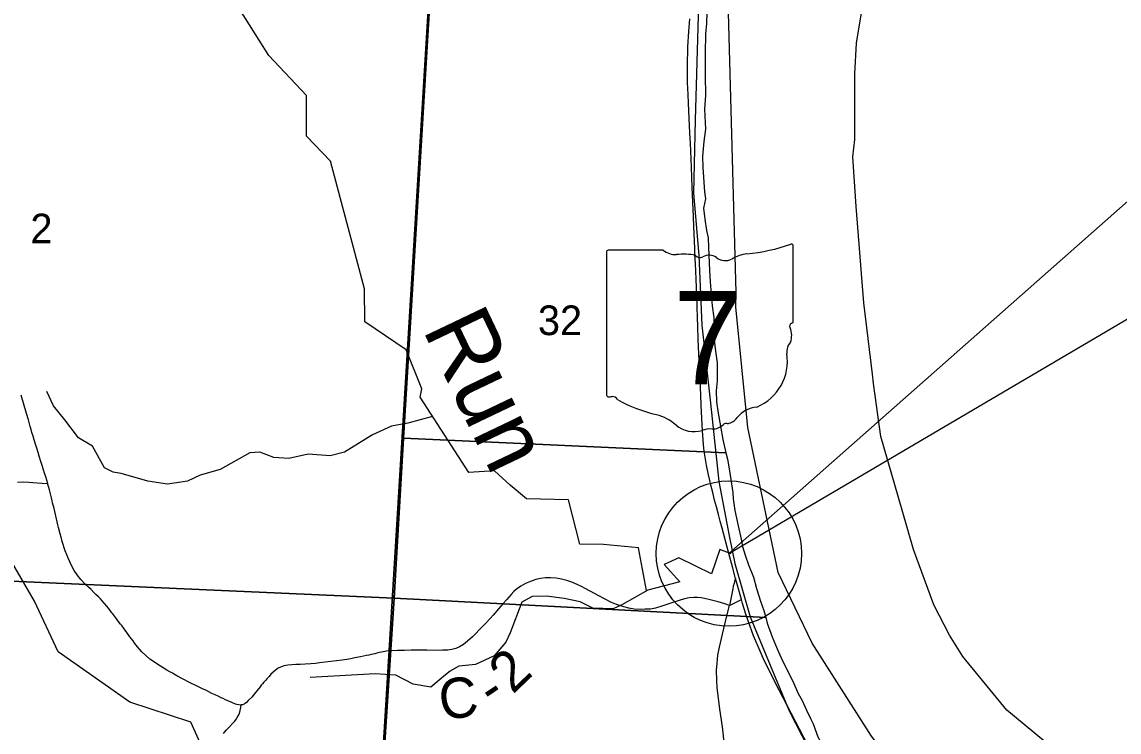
# Model space of a CAD drawing. Extents: x 21.4 to 65.3, y 4 to 26.
# Drawn here: x 25.873 to 27.421, y 21.246 to 22.248 of the extents above; entities that cross this region are included whole.
import ezdxf

# ---------------------------------------------------------------- set-up
doc = ezdxf.new("R2010")
doc.units = 0
for name, color, linetype in [('Default', 7, 'Continuous'), ('GM_X_County_Road', 7, 'Continuous'), ('GM_X_County_Road_Text', 7, 'Continuous'), ('GM_X_Interchange_Ramps', 7, 'Continuous'), ('GM_X_Major_River', 7, 'Continuous'), ('GM_X_Minor_River', 7, 'Continuous'), ('GM_X_Minor_River_Text', 7, 'Continuous'), ('GM_X_Section', 7, 'Continuous'), ('GM_X_Section_Text', 7, 'Continuous'), ('GM_X_State_Location', 7, 'Continuous'), ('GM_X_State_Route', 7, 'Continuous'), ('GM_X_State_Shield', 7, 'Continuous'), ('GM_X_Township_Road', 7, 'Continuous'), ('SH_Cut_Line', 7, 'Continuous'), ('TX_P_1', 7, 'Continuous')]:
    doc.layers.add(name, color=color, linetype=linetype)

msp = doc.modelspace()

# ---------------------------------------------------------------- linework, layer by layer
at = {"layer": 'Default'}
for points in [[(25.869, 20.4484), (25.878, 20.4484), (25.89, 20.4485), (25.896, 20.4488), (25.9007, 20.45), (25.9039, 20.4514), (25.9047, 20.4519), (26.0076, 20.4475), (26.3338, 20.4317), (26.379, 21.1689), (26.3906, 21.3613), (26.4573, 22.45)], [(26.4573, 22.45), (26.3906, 21.3613), (26.379, 21.1689), (26.8527, 21.1433), (27.0325, 21.1315), (27.1713, 21.1261), (27.125, 21.1713), (27.0715, 21.2402), (26.9875, 21.3717), (26.9395, 21.4715), (26.8968, 21.6757), (26.8802, 21.8461), (26.8806, 21.8662), (26.8662, 22.382)]]:
    msp.add_lwpolyline(points, dxfattribs=at)
at = {"layer": 'GM_X_County_Road'}
for points in [[(26.2602, 21.3414), (26.2592, 21.3414), (26.2535, 21.3412), (26.248, 21.3407), (26.242, 21.3394), (26.2374, 21.3379), (26.2342, 21.3363), (26.2297, 21.3332), (26.2239, 21.3278), (26.2213, 21.3247), (26.2183, 21.3213), (26.2167, 21.3196), (26.2138, 21.3164), (26.2118, 21.3141), (26.2103, 21.3122), (26.2088, 21.3102), (26.2043, 21.3046), (26.2004, 21.2996), (26.1968, 21.2954), (26.192, 21.2905), (26.1893, 21.288), (26.1875, 21.2867), (26.186, 21.2857), (26.1838, 21.2848), (26.1817, 21.2844), (26.1804, 21.2842), (26.1784, 21.2844), (26.1759, 21.285), (26.1741, 21.2856), (26.1689, 21.2877), (26.1655, 21.2892), (26.1599, 21.2918), (26.1565, 21.2934), (26.1537, 21.2947), (26.1497, 21.2966), (26.1452, 21.2987), (26.1407, 21.3008), (26.1362, 21.3029), (26.1328, 21.3046), (26.1272, 21.3072), (26.1228, 21.3094), (26.1161, 21.3127), (26.1139, 21.3138), (26.1091, 21.3163), (26.1064, 21.3176), (26.1027, 21.3194), (26.099, 21.3214), (26.0912, 21.3257), (26.0886, 21.3271), (26.085, 21.3292), (26.0813, 21.3312), (26.077, 21.3335), (26.0627, 21.3424), (26.0581, 21.3456), (26.053, 21.3492), (26.0472, 21.354), (26.0417, 21.3592), (26.0357, 21.3664), (26.0321, 21.3711), (26.0293, 21.3748), (26.0248, 21.3807), (26.0207, 21.3865), (26.017, 21.3917), (26.0134, 21.3963), (26.0117, 21.3984), (26.0099, 21.4009), (26.0051, 21.4072), (26.0006, 21.413), (25.9995, 21.4145), (25.9961, 21.4189), (25.9942, 21.4213), (25.9922, 21.4236), (25.9892, 21.4275), (25.9859, 21.4313), (25.9832, 21.4343), (25.9804, 21.4372), (25.9769, 21.4401), (25.9738, 21.4433), (25.9703, 21.4472), (25.9663, 21.4508), (25.9624, 21.4544), (25.9555, 21.4616), (25.9503, 21.4679), (25.9461, 21.4742), (25.9428, 21.4803), (25.9382, 21.4905), (25.9337, 21.5021), (25.9295, 21.5152), (25.9278, 21.5212), (25.9265, 21.526), (25.9241, 21.535), (25.9232, 21.5386), (25.9222, 21.5428), (25.9179, 21.5614), (25.9159, 21.5698), (25.9153, 21.5722), (25.9144, 21.5765), (25.9124, 21.5842), (25.9115, 21.5878), (25.9105, 21.5913), (25.9093, 21.5955), (25.9089, 21.5967), (25.9061, 21.6062), (25.9044, 21.6115), (25.903, 21.6162), (25.9011, 21.6222), (25.8993, 21.6281), (25.8971, 21.6352), (25.8954, 21.6406), (25.8935, 21.6465), (25.8917, 21.6524), (25.8898, 21.6583), (25.8882, 21.6636), (25.8866, 21.669), (25.8854, 21.6731), (25.8842, 21.6772), (25.8831, 21.6812), (25.8827, 21.6828), (25.8821, 21.685), (25.8816, 21.6867), (25.879, 21.6955), (25.8716, 21.7216)], [(26.871, 21.4249), (26.8643, 21.4272), (26.8552, 21.4298), (26.8439, 21.4329), (26.8359, 21.4347), (26.8309, 21.4356), (26.826, 21.4361), (26.8207, 21.436), (26.8141, 21.4354), (26.8074, 21.434), (26.8001, 21.432), (26.7912, 21.4292), (26.7755, 21.4237), (26.7666, 21.4212), (26.7596, 21.4198), (26.7522, 21.4195), (26.7451, 21.4192), (26.7365, 21.4197), (26.7292, 21.421), (26.7221, 21.423), (26.7118, 21.4261), (26.7044, 21.4292), (26.6939, 21.4344), (26.6674, 21.4486), (26.6621, 21.4515), (26.6563, 21.4545), (26.6484, 21.4576), (26.6415, 21.4599), (26.634, 21.462), (26.6265, 21.4631), (26.6184, 21.4637), (26.6113, 21.4636), (26.6044, 21.4627), (26.5978, 21.4612), (26.59, 21.4587), (26.5832, 21.4556), (26.5767, 21.4519), (26.5706, 21.4477), (26.5669, 21.4443), (26.563, 21.4402), (26.5564, 21.4327), (26.5512, 21.4269), (26.5454, 21.4204), (26.5373, 21.411), (26.5332, 21.4065), (26.5274, 21.4), (26.5229, 21.3955), (26.5178, 21.3902), (26.513, 21.3854), (26.5083, 21.3806), (26.5011, 21.3743), (26.4955, 21.3697), (26.4902, 21.3666), (26.4847, 21.3641), (26.4793, 21.3626), (26.4735, 21.3616), (26.466, 21.3615), (26.4587, 21.3614), (26.4439, 21.3616), (26.4364, 21.3616), (26.4273, 21.3616), (26.4217, 21.3616), (26.4124, 21.3614), (26.4075, 21.3614), (26.4026, 21.3613), (26.3908, 21.3608)], [(26.3908, 21.3608), (26.3898, 21.3608), (26.3869, 21.3605), (26.3846, 21.36), (26.3824, 21.3596), (26.3799, 21.3591), (26.377, 21.3582), (26.3734, 21.3573), (26.3705, 21.3566), (26.368, 21.356), (26.3653, 21.3554), (26.362, 21.3547), (26.3589, 21.354), (26.3504, 21.3523), (26.3425, 21.3508), (26.3367, 21.3496), (26.3312, 21.3487), (26.3245, 21.3477), (26.3166, 21.3467), (26.3086, 21.3457), (26.2925, 21.3437), (26.287, 21.3431), (26.2801, 21.3426), (26.2723, 21.342), (26.2652, 21.3416), (26.2602, 21.3414)], [(26.1569, 21.2441), (26.1606, 21.2487), (26.1649, 21.2532), (26.1703, 21.2587), (26.1724, 21.2612), (26.1744, 21.2635), (26.1763, 21.2665), (26.1778, 21.2689), (26.1794, 21.2723), (26.1807, 21.2764), (26.1814, 21.2808), (26.1817, 21.2844)]]:
    msp.add_lwpolyline(points, dxfattribs=at)
at = {"layer": 'GM_X_Interchange_Ramps'}
msp.add_lwpolyline([(26.8796, 21.4628), (26.8783, 21.4585), (26.8774, 21.4558), (26.8764, 21.452), (26.8756, 21.4482), (26.871, 21.4249)], dxfattribs=at)
at = {"layer": 'GM_X_Major_River'}
for points in [[(27.0481, 22.0824), (27.0477, 22.1747), (27.0502, 22.2179), (27.0687, 22.3289)], [(26.828, 22.3063), (26.8227, 22.1096), (26.8201, 22.0067), (26.8276, 21.9186), (26.8322, 21.8203), (26.8443, 21.7103), (26.8561, 21.5999), (26.8712, 21.5206), (26.8785, 21.4842), (26.9, 21.4087), (26.9282, 21.3405), (26.9553, 21.2761), (27.0003, 21.1882), (27.0406, 21.1367), (27.0531, 21.1254), (27.0975, 21.0883), (27.1373, 21.0502), (27.2306, 20.9757), (27.2878, 20.9346), (27.4011, 20.8709), (27.4242, 20.8634)], [(27.478, 21.1221), (27.3279, 21.2229), (27.2623, 21.2769), (27.2004, 21.3526), (27.1817, 21.3829), (27.1596, 21.4257), (27.1306, 21.5038), (27.1149, 21.5592), (27.0846, 21.6634), (27.0744, 21.7378), (27.0729, 21.7511), (27.0604, 21.8516), (27.05, 21.9879), (27.0452, 22.0577), (27.0481, 22.0824)]]:
    msp.add_lwpolyline(points, dxfattribs=at)
at = {"layer": 'GM_X_Minor_River'}
for points in [[(26.8733, 21.4976), (26.8574, 21.5036), (26.8454, 21.4693), (26.7995, 21.492), (26.7788, 21.4824), (26.8011, 21.4579), (26.7538, 21.4461), (26.7424, 21.506), (26.6933, 21.5108), (26.6599, 21.5113), (26.6439, 21.5738), (26.5847, 21.5751), (26.5613, 21.5947), (26.5394, 21.6146), (26.5033, 21.6124), (26.4344, 21.7188), (26.4369, 21.7302), (26.4149, 21.7854), (26.3563, 21.8251), (26.3561, 21.8715), (26.3078, 22.0517), (26.2739, 22.0871), (26.2739, 22.1444), (26.2211, 22.2005), (26.18, 22.2654)], [(26.4521, 21.6914), (26.417, 21.6821), (26.3942, 21.6779), (26.3673, 21.6653), (26.3279, 21.6413), (26.3074, 21.636), (26.2767, 21.6382), (26.2494, 21.6321), (26.2282, 21.6336), (26.2084, 21.6412), (26.194, 21.6401), (26.1523, 21.6168), (26.1243, 21.6084), (26.1061, 21.6), (26.078, 21.5958), (26.05, 21.6), (26.0128, 21.611), (26.0015, 21.6129), (25.9893, 21.6189), (25.9723, 21.6497), (25.9522, 21.6615), (25.9329, 21.6866), (25.9173, 21.7063), (25.9079, 21.7265)], [(26.157, 21.158), (26.1109, 21.2601), (26.0247, 21.2885), (25.9236, 21.3593), (25.8903, 21.4308), (25.8577, 21.4867)], [(26.7556, 21.4465), (26.719, 21.4258), (26.7069, 21.4201), (26.6784, 21.4212), (26.6602, 21.4299), (26.6375, 21.4348), (26.6128, 21.4378), (26.5928, 21.4374), (26.578, 21.4294), (26.5617, 21.3861), (26.5556, 21.3728), (26.5389, 21.3537), (26.5124, 21.3415), (26.4892, 21.3392), (26.4767, 21.332), (26.4703, 21.3267), (26.4494, 21.3095), (26.4248, 21.3137), (26.4001, 21.3266), (26.371, 21.3285), (26.2792, 21.323)]]:
    msp.add_lwpolyline(points, dxfattribs=at)
at = {"layer": 'GM_X_Section'}
for points in [[(25.4085, 22.5025), (26.4597, 22.4573), (26.4491, 22.292), (26.4111, 21.6607), (26.3977, 21.4352), (25.3384, 21.4821)], [(26.866, 21.6402), (26.868, 21.6312), (26.8711, 21.6149), (26.8738, 21.5964), (26.8757, 21.5842), (26.8761, 21.5752), (26.8785, 21.5589), (26.8831, 21.5373), (26.8877, 21.5184), (26.8892, 21.5081), (26.8935, 21.4945), (26.8977, 21.482), (26.9049, 21.4646), (26.9091, 21.4487), (26.9149, 21.4309), (26.9195, 21.4177), (26.9221, 21.4076), (26.3977, 21.4352), (26.4111, 21.6607)], [(26.3977, 21.4352), (26.3809, 21.1738), (26.3352, 20.4317), (25.2871, 20.4832), (25.275, 20.4836), (25.3384, 21.4821)], [(26.9221, 21.4076), (26.9241, 21.3999), (26.9314, 21.3806), (26.9382, 21.3636), (26.944, 21.3511), (26.9478, 21.3428), (26.9604, 21.3178), (26.968, 21.3004), (26.9734, 21.2909), (26.9795, 21.2773), (26.9856, 21.2645), (26.989, 21.258), (26.9959, 21.2395), (27.0001, 21.2319), (27.0104, 21.2145), (27.0191, 21.1998), (27.0267, 21.1877), (27.0351, 21.1771), (27.0481, 21.1643), (27.069, 21.1431), (27.0754, 21.136), (27.0797, 21.131), (26.3809, 21.1738), (26.3977, 21.4352)]]:
    msp.add_lwpolyline(points, close=True, dxfattribs=at)
msp.add_lwpolyline([(26.8389, 22.2616), (26.8386, 22.2457), (26.8371, 22.2309), (26.8368, 22.2047), (26.8365, 22.1725), (26.837, 22.1445), (26.8356, 22.1252), (26.8372, 22.0967), (26.8346, 22.0793), (26.8328, 22.0588), (26.8336, 22.0426), (26.8356, 22.0085), (26.8371, 21.9986), (26.8345, 21.9853), (26.8361, 21.9698), (26.8384, 21.9539), (26.8411, 21.9433), (26.8412, 21.9297), (26.8428, 21.8975), (26.8436, 21.8812), (26.8464, 21.8475), (26.8487, 21.8308), (26.8484, 21.8069), (26.8515, 21.7838), (26.8535, 21.7672), (26.8536, 21.7418), (26.8521, 21.7274), (26.8529, 21.7122), (26.8549, 21.6959), (26.8583, 21.6778), (26.8618, 21.6588), (26.866, 21.6402), (26.4111, 21.6607), (26.4491, 22.292)], dxfattribs=at)
at = {"layer": 'GM_X_State_Route'}
for points in [[(26.8796, 21.4628), (26.8752, 21.4793), (26.8702, 21.498), (26.8606, 21.534), (26.858, 21.5435), (26.8554, 21.5531), (26.8526, 21.5639), (26.8501, 21.5735), (26.8474, 21.5843), (26.8449, 21.5945), (26.8433, 21.6011), (26.8415, 21.6089), (26.8385, 21.6229), (26.8366, 21.634), (26.8352, 21.6426), (26.8342, 21.6519), (26.833, 21.6711), (26.8311, 21.7071), (26.8304, 21.7214), (26.8297, 21.7431), (26.8289, 21.7604), (26.8279, 21.7796), (26.8269, 21.8001), (26.8263, 21.8188), (26.8258, 21.8305), (26.8248, 21.8628), (26.8244, 21.8734), (26.8238, 21.8852), (26.8233, 21.8963), (26.8229, 21.9069), (26.8223, 21.9205), (26.822, 21.9286), (26.8216, 21.9392), (26.8207, 21.9596), (26.82, 21.9732), (26.8185, 22.0148), (26.8174, 22.0434), (26.8158, 22.0769), (26.8152, 22.0912), (26.8131, 22.1334), (26.8126, 22.1458), (26.812, 22.1625), (26.8118, 22.175), (26.8119, 22.1836), (26.8119, 22.193), (26.8121, 22.2055), (26.8124, 22.2129), (26.8136, 22.2347), (26.815, 22.2526)], [(27.0327, 21.131), (27.0255, 21.1434), (27.0182, 21.1571), (27.0099, 21.173), (26.9818, 21.2278), (26.9582, 21.2729), (26.9412, 21.3054), (26.929, 21.3292), (26.9187, 21.3505), (26.9113, 21.3669), (26.9051, 21.3819), (26.9, 21.3953), (26.8945, 21.4112), (26.8893, 21.4278), (26.8879, 21.433), (26.8826, 21.4517), (26.8796, 21.4628)], [(26.864, 21.2277), (26.861, 21.2536), (26.8575, 21.2786), (26.8554, 21.2939), (26.8538, 21.3085), (26.853, 21.319), (26.8529, 21.3334), (26.8535, 21.3434), (26.8548, 21.3547), (26.8568, 21.366), (26.8611, 21.3841), (26.8675, 21.41), (26.871, 21.4249), (26.8776, 21.428), (26.8841, 21.4312), (26.8879, 21.433)]]:
    msp.add_lwpolyline(points, dxfattribs=at)
at = {"layer": 'GM_X_State_Shield'}
for p, q in [((26.6975, 21.9228), (26.6975, 21.7227)), ((26.7773, 21.9262), (26.7, 21.9262)), ((26.9611, 21.8265), (26.9611, 21.9312)), ((26.9611, 21.8265), (26.9611, 21.8265))]:
    msp.add_line(p, q, dxfattribs=at)
for centre, radius, start, end in [((26.7005, 21.9232), 0.00305, 98.1301, 188.1301), ((26.7957, 21.9494), 0.0296, 231.6195, 271.1119), ((26.8672, 22.199), 0.2796, 275.8445, 288.9065), ((26.9582, 21.9316), 0.00294, 351.8621, 97.738), ((26.8055, 21.8139), 0.1064, 80.4867, 94.9883), ((26.8296, 21.9242), 0.00855, 219.7921, 297.1024), ((26.8422, 21.9011), 0.0178, 54.4667, 119.1411), ((26.8651, 21.9328), 0.0214, 233.8562, 294.8282), ((26.9029, 21.8651), 0.0563, 97.3462, 120.7689), ((26.9604, 21.8188), 0.00454, 107.944, 210.337), ((26.9315, 21.8056), 0.0273, 340.033, 23.6496), ((26.958, 21.8261), 0.00314, 289.6038, 7.7341), ((26.9716, 21.7827), 0.0198, 136.8065, 186.9296), ((26.8829, 21.7694), 0.0699, 292.3089, 8.9858), ((26.7005, 21.7222), 0.00308, 171.9584, 258.3066), ((26.701, 21.7427), 0.0235, 267.339, 280.6039), ((26.7058, 21.7111), 0.00848, 29.7484, 93.2717), ((26.8128, 21.8909), 0.2019, 240.4129, 257.1985), ((26.7526, 21.6327), 0.0632, 47.1842, 75.836), ((26.9124, 21.6665), 0.0383, 94.4031, 142.5768), ((26.821, 21.7101), 0.0401, 230.7004, 286.2918), ((26.8471, 21.6951), 0.0214, 268.777, 315.5493), ((26.8664, 21.6757), 0.00601, 65.7517, 132.6484), ((26.8638, 21.7033), 0.0226, 282.8732, 323.2771), ((26.8441, 21.6409), 0.0329, 85.6951, 111.2099)]:
    msp.add_arc(centre, radius, start, end, dxfattribs=at)
at = {"layer": 'GM_X_Township_Road'}
msp.add_lwpolyline([(25.8665, 21.5988), (25.8752, 21.599), (25.8821, 21.5987), (25.8881, 21.5985), (25.9004, 21.5974), (25.9089, 21.5967)], dxfattribs=at)
at = {"layer": 'SH_Cut_Line'}
msp.add_lwpolyline([(28.1702, 20.2638), (28.0527, 20.4505), (27.9586, 20.5583), (27.8546, 20.6506), (27.8422, 20.6714), (27.7163, 20.7618), (27.578, 20.8563), (27.4195, 20.94), (27.2824, 21.0623), (27.2266, 21.087), (27.1713, 21.1261), (27.125, 21.1713), (27.0715, 21.2402), (26.9875, 21.3717), (26.9395, 21.4715), (26.8968, 21.6757), (26.8802, 21.8461), (26.8806, 21.8662), (26.8662, 22.382)], dxfattribs=at)
at = {"layer": 'TX_P_1'}
msp.add_lwpolyline([(27.691, 22.2228), (26.8702, 21.498), (27.691, 21.9812)], close=True, dxfattribs=at)
msp.add_circle((26.8702, 21.498), 0.1025, dxfattribs=at)

# ---------------------------------------------------------------- texts
at = {"layer": 'GM_X_County_Road_Text'}
for s, rotation, p in [('2', 43.8461, (26.5651, 21.2986)), ('C', 7.704, (26.4648, 21.2626)), ('-', 33.7753, (26.5372, 21.2788))]:
    msp.add_text(s, height=0.0568, rotation=rotation, dxfattribs=at).set_placement(p)
at = {"layer": 'GM_X_Minor_River_Text'}
msp.add_text('Run', height=0.0947, rotation=295.5123, dxfattribs=at).set_placement((26.4371, 21.8149))
at = {"layer": 'GM_X_Section_Text'}
for s, height, p in [('2', 0.0419, (25.8845, 21.9357)), ('32', 0.04186, (26.6007, 21.8062))]:
    msp.add_text(s, height=height, rotation=0, dxfattribs=at).set_placement(p)
at = {"layer": 'GM_X_State_Location'}
for s in ['s', 'r']:
    msp.add_text(s, height=0.000189, dxfattribs=at).set_placement((26.8263, 21.8094))
msp.add_text('7', height=0.000189, rotation=0, dxfattribs=at).set_placement((26.7978, 21.7956))
at = {"layer": 'GM_X_State_Shield'}
msp.add_text('7', height=0.1318, dxfattribs=at).set_placement((26.7915, 21.7368))

doc.saveas('drawing.dxf')
